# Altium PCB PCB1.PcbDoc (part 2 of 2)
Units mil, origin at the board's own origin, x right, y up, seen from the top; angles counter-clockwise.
Board outline 1968.5 x 1968.5 mil, 2 copper layers (Top Layer, Bottom Layer); 81 components, 57 nets, 327 pads, 270 vias.
Unrouted connection lines stored in the file: 104.
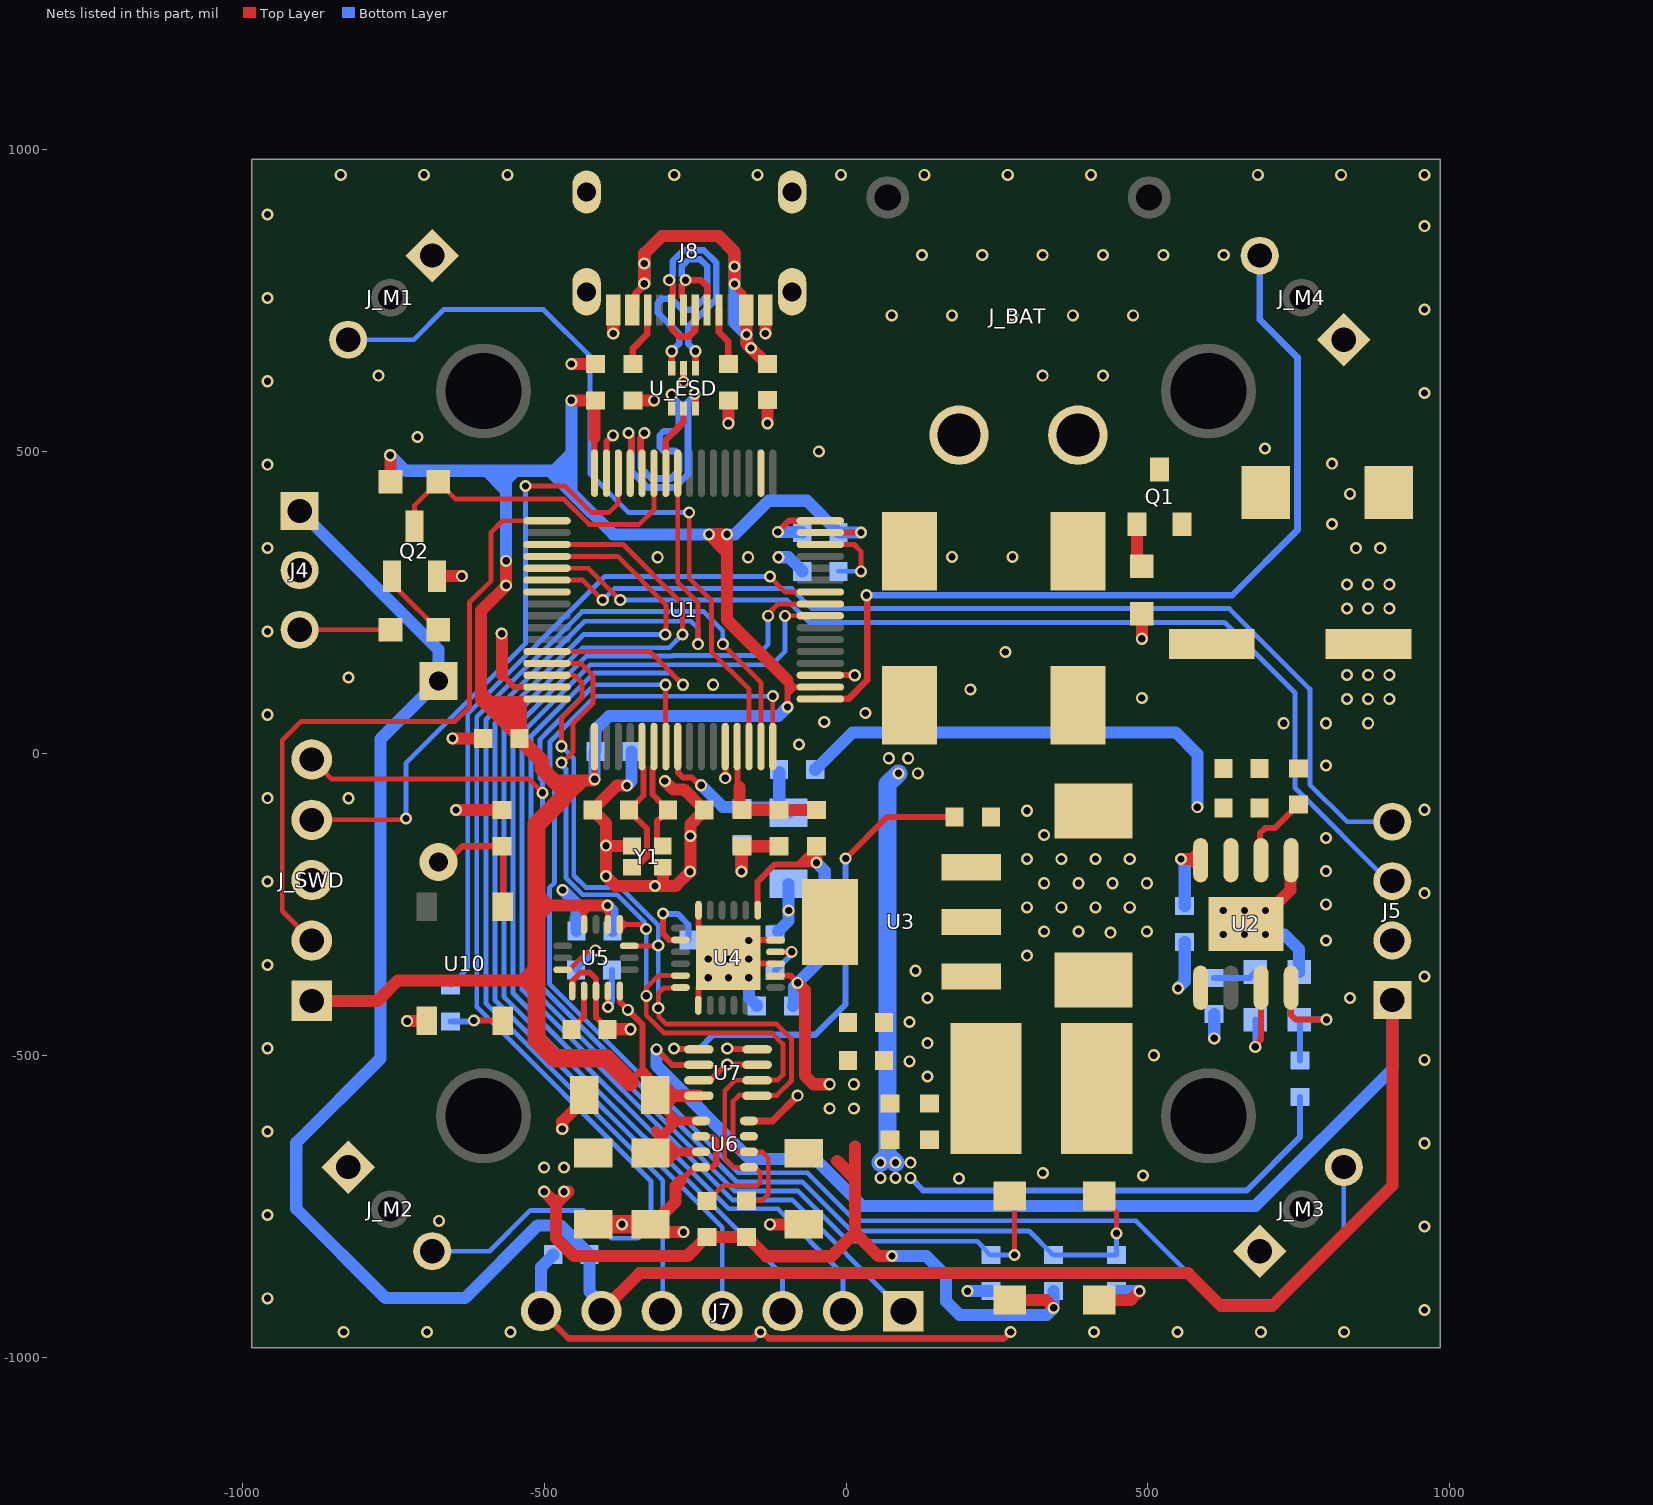
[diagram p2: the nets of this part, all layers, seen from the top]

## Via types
v1: diameter 20, hole 12, Top Layer to Bottom Layer, tented both sides, 270 vias

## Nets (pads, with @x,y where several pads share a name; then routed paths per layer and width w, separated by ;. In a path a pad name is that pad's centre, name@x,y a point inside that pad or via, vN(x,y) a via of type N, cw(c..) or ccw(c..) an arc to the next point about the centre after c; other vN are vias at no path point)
+3.3V: C_BMP1.1 C_BMP2.1 C_BULK.1 C_CS.1 C_INA.1 C_LDO_OUT.1 C_VDD1.1 C_VDD2.1 C_VDD3.1 C_VDD4.1 C_VLOGIC.1 CAP_BYPASS.1 FB2.1 J_SWD.1 R2.1 R4.1 R21.1 R_NRST.1 SW_BOOT.2 U1.1 U1.18 U1.31 U1.48 U1.64 U3.2 U3.4 U4.8 U4.13 U5.2 U5.4 U5.13 U6.2 U6.6 U6.8 U7.4 | length 7789
  Top Layer w10: -604.69,108.07 -586.81,90.19 ; -586.81,71.52 -586.81,90.19 ; -541.08,77.35 U1.64@-528.24,90.19 ; U1.64@-495.27,90.19 U1.64@-528.24,90.19 ; -446.45,-251.97 -434.04,-264.38 ; -432,-251.97 -433.66,-253.63 -433.66,-264 ; -421.63,-251.97 -433.66,-264 ; U1.1@-416.54,11.46 -416.41,11.33 -416.41,-42.64 v1(-416.29,-42.76) ; U1.48@-416.54,464.2 -416.54,523.83 ; -407.41,-251.04 -406.47,-251.97 -395,-263.44 ; v1(-395,-251.97) -394.64,-252.33 -394.64,-283.23 U5.2@-394.45,-283.42 ; U5.13@-374.9,-393.47 U5.13@-374.75,-393.62 U5.13@-374.75,-393.62 -374.71,-411.55 v1(-361.47,-424.79) ; v1@-360.87,-424.79 v1(-361.47,-424.79) ; -349.31,-535 -337,-522.69 ; -337,-533 -337,-522.69 ; -325.69,-534 -337,-522.69 ; U4.13@-146.28,-259.78 -146.28,-212.28 -117.72,-183.72 -79.39,-183.72 ; U4.8@-116.75,-368.05 -116.55,-368.25 -91.75,-368.25 v1(-80,-380) ; v1(-97,77) -97,98.32 ; v1(-49,-181) -51.72,-183.72 -63.16,-183.72 ; -49,-169.56 -59.39,-179.95 ; FB2.1@-49,-158.12 -53.79,-158.12 FB2.1@-59.39,-163.72 ; U1.18@-42.88,110.22 -86.22,110.22 -97,121 -97,98.32 ; U1.18@-42.53,109.88 U1.18@-42.53,109.88 -85.5,109.82 -97,98.32 ; U1.31@-42.53,365.78 v1(24.78,365.78) ; -586.81,90.19 U1.64@-528.24,90.19 ; -434.04,-264.38 -433.66,-264 ; -434.04,-264.38 -434.04,-283.23 U5.4@-433.85,-283.42 -433.66,-283.23 -433.66,-264 ; v1(-361.47,-424.79) -337,-449.26 -337,-522.69 ; -79.39,-183.72 -69.39,-173.72 ; -79.39,-183.72 -63.16,-183.72 ; -69.39,-173.72 FB2.1@-59.39,-163.72 ; -69.39,-173.72 -63.16,-179.95 -63.16,-183.72 ; -63.16,-183.72 -59.39,-179.95 ; -59.39,-179.95 FB2.1@-59.39,-163.72
  Top Layer w15: v1(-416.29,-42.76) -429.26,-42.76 ; C_BMP2.1@-323.69,-661.91 -321.79,-660 -280.89,-660 ; -315.82,-625.07 -305.99,-634.91 ; C_INA.1@-315.82,-566 -315.82,-573.87 -280.89,-608.8 ; C_BMP2.1@-315.31,-644.23 -305.99,-634.91 ; C_BMP2.1@-296.94,-677.06 -280.39,-660.51 ; -291.29,-608.8 -280.89,-608.8 ; -280.39,-609.31 -305.99,-634.91 ; U6.6@-240.27,-660 -280.89,-660 ; U6.8@-240.26,-608.8 -280.89,-608.8 ; -429.26,-42.76 -431.5,-45 -461,-74.5 -469.5,-74.5 -440,-45 -437.76,-42.76 -429.26,-42.76 ; -305.99,-634.91 -280.89,-660
  Top Layer w20: J_SWD.1@-885,-410 -776,-410 -742,-376 -536.25,-376 ; v1(-755,494) -754.37,493.37 R21.1@-754.37,450 ; v1(-563,319) v1(-563,278) -604.69,236.31 -604.69,108.07 -604.69,89.4 -586.81,71.52 C_VDD1.1@-541.08,25.79 ; -513,-396.65 -533.65,-376 -536.25,-376 ; -513,-352.75 -536.25,-376 ; -513,-274 -513,-273.55 -491.42,-251.97 ; -513,-244 -505.03,-251.97 -491.42,-251.97 ; -513,-227 -513,-230.39 -491.42,-251.97 ; v1(-500,-726) -480.31,-745.69 -480.31,-802.98 -450.71,-832.57 -262.44,-832.57 -235.75,-805.88 -234.96,-805.88 R4.1@-230,-800.92 -229.96,-800.88 -165.04,-800.88 R2.1@-165,-800.84 -164.21,-800.84 -132.06,-833 -24,-833 15,-794 ; -482.67,-46.36 -481.31,-45 -440,-45 -431.5,-45 -418.53,-45 v1(-416.29,-42.76) ; -476.68,-742.68 v1@-460,-726 ; -469.5,-74.5 -469.5,-59.53 ; v1(-455,585) C_VDD3.1@-415,585 -416.54,583.46 -416.54,523.83 ; v1(-395,-251.97) -406.47,-251.97 -421.63,-251.97 -432,-251.97 -446.45,-251.97 -491.42,-251.97 ; C_INA.1@-315.82,-566 -314.76,-567.06 -284.28,-567.06 ; C_INA.1@-300.7,-583.48 -284.28,-567.06 ; C_INA.1@-300.7,-550.64 -284.28,-567.06 ; U7.4@-243.76,-567.06 -284.28,-567.06 ; -97,121 -197,221 -197,333 ; v1(-80,-380) -67.86,-392.14 -67.86,-533.84 -53.7,-548 v1(-27,-548) ; v1(-49,-181) -49,-169.56 -49,-158.12 FB2.1@-48.64,-157.76 ; U3.4@-48.64,-257.15 U3.4@-26.57,-279.21 ; -15,-675 15,-705 ; 15,-651 15,-705 ; v1(76,-832.58) 53.58,-832.58 15,-794 ; SW_BOOT.2@271,-905.25 330.85,-905.25 v1(344,-918.4) ; -197,333 v1(-197,363) v1(-227,363) -197,333 ; 15,-794 15,-705
  Top Layer w25: -576,80 -574,78 -570,78 -569.35,77.35 ; -469.5,-59.53 -482.67,-46.36 -503.26,-25.77 -503.26,-13.6 -541.08,24.21 C_VDD1.1@-541.08,25 -541.08,25.79 -541.08,49.08 ; -569.35,77.35 -541.08,49.08 ; -569.35,77.35 -541.08,77.35 -541.08,49.08
  Top Layer w30: -513,-274 -513,-352.75 -513,-396.65 -513,-474.3 -482.29,-505.01 -396.99,-505.01 -358,-544 ; -513,-273.55 -513,-244 -513,-230.39 ; -513,-227 -513,-118 -469.5,-74.5
  Bottom Layer w20: v1(-755,494) -729.22,468.22 -596,468.22 ; v1(-563,278) v1(-563,319) -563,438 ; v1(-455,585) -455,497 ; v1(-416.29,-42.76) C_VDD2.1@-416.29,1.63 ; C_VDD2.1@-414.92,3 -414.92,39.82 -392.9,61.84 -112.16,61.84 v1(-97,77) ; v1(-395,-251.97) -386.61,-260.37 CAP_BYPASS.1@-386.61,-294.38 ; C_VLOGIC.1@-88,-418 -86.43,-416.43 -86.43,-386.43 v1(-80,-380) -35.17,-335.17 -35.17,-194.83 v1(-49,-181) ; v1(24.78,365.78) C_VDD4.1@-12.61,365.78 -12.61,366.56 -64.61,418.56 -128.44,418.56 -184,363 v1(-197,363) v1(-227,363) -385.83,363 -455,432.17 ; v1(76,-832.58) 133.18,-832.58 166,-865.4 166,-908 188,-930 333,-930 v1@344,-919 ; v1(344,-918.4) R_NRST.1@344,-890.84 ; -596,468.22 -565.78,438 -563,438 ; -596,468.22 -564.22,468.22 ; -564.22,468.22 -563,467 -563,452.5 ; -564.22,468.22 -547.28,468.22 ; -563,438 -563,452.5 ; -563,452.5 -547.28,468.22 ; -547.28,468.22 -491.05,468.22 ; -491.05,468.22 -473.03,450.2 ; -491.05,468.22 -483.78,468.22 ; -483.78,468.22 -468.78,468.22 -455,482 ; -483.78,468.22 -455,497 ; -473.03,450.2 -455,468.22 ; -473.03,450.2 -455,432.17 ; -455,432.17 -455,468.22 ; -455,468.22 -455,482 ; -455,482 -455,497
  other v1: -467,-726 -500,-686 -467,-686 -27,-588 13,-588 13,-548
+5V_SYS: C_LORA.1 D5.1 J4.1 J5.1 J7.6 U7.2 | length 5448.2
  Top Layer w10: v1(-313.97,-490.14) -288.24,-515.87 U7.2@-243.76,-515.87
  Top Layer w20: J7.6@-405,-924 -341.92,-860.92 566.92,-860.92 620.96,-914.96 706.04,-914.96 905,-716 J5.1@905,-408.43
  Bottom Layer w20: J4.1@-905,401.85 -675,171.85 D5.1@-675,120 -771,24 -771,-505.27 -910.69,-644.96 -910.69,-754.31 -763,-902 -631,-902 -511,-782 -473.08,-782 -430.83,-824.25 -430.04,-824.25 -425.08,-829.21 -425.08,-891.22 -405,-911.3 J7.6@-405,-924 ; v1(-313.97,-490.14) -313.97,-517.1 -159.19,-671.89 -50.95,-671.89 26.65,-749.49 678.51,-749.49 905,-523 J5.1@905,-408.43
BOOT0: R_BOOT.1 SW_BOOT.1 U1.60 | length 2053.4
  Top Layer w8: U1.60@-495.27,168.93 -325.11,168.93 v1(-270,113.82) ; SW_BOOT.1@271,-733.21 279,-741.21 v1(279,-831)
  Bottom Layer w8: v1(-270,113.82) -289.18,133 -417.54,133 -521.67,28.86 -521.67,-387.98 -184.92,-724.74 -79.77,-724.74 3.73,-808.23 217.23,-808.23 228.25,-819.25 228.25,-820.04 239.21,-831 v1(279,-831)
BST: C_BST.1 U2.8 | length 151
  Top Layer w15: U2.8@582.92,-187.75 570.17,-175 582.92,-162.25 U2.8@582.92,-160.87
  Top Layer w20: v1(555,-175) 570.17,-175 585.34,-175 587.29,-176.95 U2.8@587.56,-176.95
  Bottom Layer w20: v1(555,-175) 561.13,-181.13 C_BST.1@561.13,-252.64
GND: C1.2 C2.2 C3.2 C5.2 C6.2 C7.2 C8.2 C14.2 C22.2 C_BMP1.2 C_BMP2.2 C_BULK.2 C_COMP.2 C_CPOUT.1 C_CS.2 C_INA.2 C_LDO_IN.2 C_LDO_OUT.2 C_LORA.2 C_NRST.2 C_REGOUT.2 C_RES.2 C_VBUS.2 C_VCAP.2 C_VDD1.2 C_VDD2.2 C_VDD3.2 C_VDD4.2 C_VDDA1.2 C_VDDA2.2 C_VLOGIC.2 CAP_BYPASS.2 D1.2 D2.2 J4.2 J5.2 J7.7 J8.1 J8.2 J8.3 J8.4 J8.A1B12 J8.B1A12 J_BAT.2 J_M1.1 J_M2.1 J_M3.1 J_M4.1 J_SWD.3 Q2.2 R1.2 R3.2 R7.2 R_BOOT.2 R_CC1.2 R_CC2.2 R_FREQ.2 SW_RST.2 U1.12 U1.19 U1.32 U1.47 U1.63 U2.5 U2.9 U3.1 U4.1 U4.9 U4.11 U4.18 U4.25 U5.9 U5.11 U6.1 U6.5 U6.7 U7.3 U7.7 U7.8 U10.3 U_ESD.2 Y1.2 Y1.4 | length 5612
  Top Layer w10: -570,129.92 -569.21,129.92 -559.25,119.96 -559.25,119.49 -549.64,109.88 U1.63@-495.27,109.88 ; J7.7@-505,-924 -459.75,-969.25 -155.04,-969.25 -144.24,-958.45 v1(-141.53,-958.45) -138.82,-958.45 -128.02,-969.25 261.94,-969.25 272.75,-958.45 v1(272.8,-958.45) ; U5.9@-453.55,-393.62 -453.36,-393.43 -453.36,-377.21 -439.12,-362.97 -424.59,-362.97 -414.15,-373.41 -414.15,-393.24 U5.11@-413.96,-393.43 ; U5.11@-414.15,-393.62 -414.15,-437.09 C_RES.2@-395.08,-456.16 ; U1.47@-396.85,464.2 -396.85,516.52 -386.37,527 v1(-386,527) ; -273.83,-708.17 -253.4,-687.75 -251.53,-687.75 -249.38,-685.6 U6.5@-240.26,-685.6 -239.44,-684.78 -220.73,-684.78 -214.95,-679 -214.95,-641.08 -220.81,-635.22 -239.44,-635.22 U6.7@-240.27,-634.4 ; v1(-269,615.53) U_ESD.2@-269,638.17 ; U4.1@-244.7,-417.26 -244.5,-417.06 -244.5,-388.02 U4.25@-195,-338.52 ; U4.18@-244.39,-259.78 -244.19,-259.98 -244.19,-289.33 U4.25@-195,-338.52 ; U7.3@-243.76,-541.46 -224.99,-541.46 -198.82,-515.29 v1(-196.77,-515.29) -196.48,-515.58 -147.51,-515.58 U7.7@-147.22,-515.87 ; v1(-200,-41) U1.12@-200,11.46 ; v1@-199,-489 -198.36,-489.64 -147.86,-489.64 U7.8@-147.22,-490.28 ; U4.9@-116.75,-348.36 -185.16,-348.36 U4.25@-195,-338.52 ; U4.11@-116.75,-308.99 -165.47,-308.99 U4.25@-195,-338.52 ; v1(-113,367) -94.53,385.47 U1.32@-42.53,385.47 ; U1.19@-42.53,129.56 v1(14.44,129.56)
  Top Layer w12: U6.1@-160.87,-608.8 -121.8,-608.8 v1(-80,-567)
  Top Layer w20: v1(-726.98,-443.54) -695.51,-443.54 U10.3@-694.57,-442.6 ; Q2.2@-677.6,293.66 v1(-636.34,293.66) ; v1(-652,25) C_VDD1.2@-600.92,25 ; v1(-646,-93.91) C22.2@-570,-93.91 ; v1(-570.44,198.43) -570,198 -570,129.92 ; v1(-470,-622) -470,-609.95 -433.93,-573.87 C_INA.2@-433.93,-566 C_INA.2@-433.93,-558.13 ; v1(-455,645) -454.84,644.84 C_VDD3.2@-415,644.84 ; C8.2@-419.48,-93.13 -379.73,-53.37 v1(-362.68,-53.37) ; C_BMP1.2@-418.69,-780.02 C_BMP1.2@-410.82,-780.02 ; C8.2@-414.52,-99.66 -413.73,-99.66 -397.68,-115.72 v1@-397.68,-158.37 ; -397.68,-180.87 -397.68,-183.53 ; C_RES.2@-395.08,-456.94 v1(-357,-456.94) ; v1(-385.55,695.45) J8.B1A12@-385.55,734.44 ; Y1.4@-354.68,-153.27 -392.58,-153.27 v1@-397.68,-158.37 ; R_CC2.2@-353,585 v1(-317.74,585) ; -303.48,-219.41 Y1.2@-303.48,-188.67 ; v1(-300.18,-45.87) -286.17,-59.88 -268.04,-59.88 -239.76,-88.17 -239.76,-88.95 C7.2@-234.8,-93.91 -239.76,-98.87 -239.76,-99.66 -257.68,-117.58 v1@-257.68,-196.13 ; -273.83,-708.17 -282.2,-716.54 -282.2,-742.68 -302.2,-762.68 -302.2,-766.39 -315.82,-780.02 -319.53,-780.02 C_BMP2.2@-323.69,-780.02 -310.71,-793 v1(-269,-793) ; v1(-258.35,-195.81) -281.95,-219.41 -381.64,-219.41 v1(-397.68,-203.37) -397.68,-183.53 ; v1(-195,547) R_CC1.2@-195,585 ; v1(-172.93,-195.5) -172.64,-195.21 -172.64,-158.72 C_VDDA1.2@-172.64,-157.76 ; C_VDDA1.2@-172.64,-153.76 C_VDDA2.2@-110.64,-153.76 ; v1(-133.59,695.45) J8.A1B12@-133.59,734.44 ; v1(-130,547) C_VBUS.2@-130,585.16 ; v1(-126.06,-780.06) C_CS.2@-70,-780.06 C_CS.2@-56.38,-793.68 ; SW_RST.2@419.68,-905.25 471.75,-905.25 v1(486.16,-890.84) ; v1(490,190) R1.2@490,231.26 ; U2.9@662.56,-282.56 680.08,-282.56 736.64,-226 736.64,-177.87 U2.5@737.56,-176.95 ; -397.68,-183.53 v1@-397.68,-158.37
  Top Layer w30: C_BMP1.2@-418.69,-780.02 C_BMP2.2@-319.53,-780.02
  Bottom Layer w10: J7.7@-505,-924 -459.75,-969.25 -152.39,-969.25 v1(-141.53,-958.45) v1(-141.53,-958.45) -138.82,-958.45 -128.02,-969.25 261.94,-969.25 272.75,-958.45 v1(272.8,-958.45)
  Bottom Layer w20: J7.7@-505,-924 -505,-850.87 -484.92,-830.79 C_LORA.2@-484.92,-830 ; v1(-469.38,-226.25) -446.45,-249.18 CAP_BYPASS.2@-446.45,-294.38 ; v1(-362.68,-53.37) -355.08,-45.77 C_VDD2.2@-355.08,3 ; C_CPOUT.1@-201,-309 -162,-309 v1(-161,-310) ; v1(-172.93,-195.5) -172.64,-195.21 R7.2@-172.64,-149.88 ; v1(-161,-371.42) -161,-404.06 -147.84,-417.21 C_VLOGIC.2@-147.84,-418 ; v1(-113,367) -73.67,367 C_VDD4.2@-72.45,365.78 ; C_REGOUT.2@-112.25,-295.2 -112.25,-294.41 -95,-277.16 v1(-95,-260) C14.2@-95,-216.02 ; v1(-112,325) -94.94,325 -72.45,302.51 C_VCAP.2@-72.45,301.73 ; v1(201.16,-890.84) R_BOOT.2@240,-890.84 ; C_NRST.2@448,-890.84 v1(486.16,-890.84) ; v1(610,-472) C_COMP.2@610,-431.55 ; v1(695,-300) 726.18,-300 750.47,-324.29 750.47,-361.73 R3.2@751,-362.26
  other v1: -832.08,-958.45 -693.97,-958.45 -555.86,-958.45 410.91,-958.45 549.02,-958.45 687.13,-958.45 825.24,-958.45 958.45,-921.97 -958.45,-902.72 958.45,-783.86 -371.19,-780.02 -674.25,-774.25 -958.45,-764.61 187,-704 492,-699 326,-695 958.45,-645.75 -958.45,-626.5 135,-535 105,-510 958.45,-507.64 510,-500 -196.77,-489 -958.45,-488.39 135,-480 105,-445 135,-405 835,-405 -228,-371.42 -194.5,-371.42 958.45,-369.53 115,-360 -958.45,-350.28 -228,-340.71 -194.5,-340.71 -161,-340.71 300,-335 795,-310 625,-300 660,-300 438.33,-296.89 328.33,-295 385,-295 498.33,-295 625,-260 660,-260 695,-260 300,-255 356.67,-255 413.33,-255 470,-255 795,-250 958.45,-231.42 -316.48,-219.41 328.33,-215 385,-215 441.67,-215 498.33,-215 -958.45,-212.17 795,-195 300,-175 356.67,-175 413.33,-175 470,-175 -397.71,-152.78 795,-140 -257.82,-136.68 328.33,-135 300,-95 958.45,-93.31 -958.45,-74.06 -824.25,-74.25 795,-20 -78,15 725,50 795,50 865,50 -36,52 -958.45,64.05 32,67 830,90 865,90 900,90 490,92 206,106 -220,113.82 -824.25,125.75 830,130 865,130 900,130 264,168 -958.45,202.16 830,240 865,240 900,240 830,280 865,280 900,280 -312,325 -162,325 175.75,325.75 275.75,325.75 845,340 885,340 -958.45,340.27 805,380 835,430 -958.45,478.38 805,480 -45,500 694,505 -710,524 958.45,597.24 -958.45,616.49 -774.25,625.75 325.75,625.75 425.75,625.75 75.75,725.75 175.75,725.75 275.75,725.75 375.75,725.75 475.75,725.75 958.45,735.35 -958.45,754.6 125.75,825.75 225.75,825.75 325.75,825.75 425.75,825.75 525.75,825.75 625.75,825.75 958.45,873.46 -958.45,892.71 -836.98,958.45 -698.87,958.45 -560.76,958.45 -284.54,958.45 -146.43,958.45 -8.32,958.45 129.79,958.45 267.9,958.45 406.01,958.45 682.23,958.45 820.34,958.45 958.45,958.45
GPS_RX: J5.4 U1.54 | length 1674.4
  Top Layer w8: U1.54@-495.27,287.04 -436.04,287.04 v1(-403,254)
  Bottom Layer w8: v1(-403,254) -384,273 -89.67,273 -56.7,240.03 635.06,240.03 768.52,106.57 768.52,-51.55 830.12,-113.15 J5.4@905,-113.15
GPS_TX: J5.3 U1.53 | length 1707.2
  Top Layer w8: U1.53@-495.27,306.73 -426.73,306.73 v1(-374,254)
  Bottom Layer w8: v1(-374,254) -97.58,254 -60.7,217.13 626.98,217.13 744,100.1 744,-57.28 898.29,-211.58 J5.3@905,-211.58
I2C1_SCL: R4.2 U1.61 U4.23 U5.1 U6.4 U7.6 | length 1613.2
  Top Layer w8: U1.61@-495.27,149.25 -439.25,149.25 -418.86,128.86 -418.86,82.84 -452,49.7 -452,2.52 -469.84,-15.31 v1@-470.93,-15.31 ; U5.1@-374.75,-283.42 -365.36,-283.42 ; U5.1@-372.99,-291.05 -365.36,-283.42 ; U5.1@-372.99,-275.61 -372.99,-275.79 -365.36,-283.42 ; v1(-331,-291) -333.43,-291 -341.01,-283.42 -365.36,-283.42 ; v1(-330.79,-401.57) -330.12,-400.91 -330.12,-387.12 -311.05,-368.05 U4.23@-274.23,-368.05 ; v1@-330.79,-398.32 -330.79,-433.85 -301.64,-463 -123,-463 -104.45,-481.55 -104.45,-532.45 -112.73,-540.73 U7.6@-145,-540.73 ; R4.2@-230,-741.08 -229.21,-741.08 -204.17,-716.04 -147.86,-716.04 -142,-710.18 -142,-693.61 -147.86,-687.75 -149.6,-687.75 -151.75,-685.6 -185.65,-685.6 -200.95,-670.3 -200.95,-559.12 -183.29,-541.46 -145.46,-541.46 U7.6@-145,-541
  Bottom Layer w8: v1(-471.24,-15.31) -471.24,-18.56 -464,-25.81 -464,-206.17 -436.2,-233.97 -379.17,-233.97 -333.3,-279.84 -333.3,-288.7 v1(-331,-291) ; v1@-330.89,-291.11 -330.89,-401.47 v1(-330.79,-401.57)
I2C1_SDA: R2.2 U1.62 U4.24 U5.16 U6.3 U7.5 | length 1493.5
  Top Layer w8: U1.62@-495.27,129.56 -450.45,129.56 -437.16,116.27 -437.16,92.06 -471.24,57.98 v1(-471.24,11.87) ; U5.16@-359.05,-318.82 -311.82,-318.82 v1(-311,-318) ; U4.24@-274.23,-387.73 -274.81,-388.31 -287.18,-388.31 -287.59,-388.72 -302.17,-388.72 -311,-397.55 v1(-311,-422) -310.07,-422.93 -310.07,-436.18 -297.79,-448.47 -114.53,-448.47 -90.54,-472.46 -90.54,-542.61 -114.5,-566.57 -146.73,-566.57 U7.5@-147.22,-567.06 ; R2.2@-165,-741 -139.45,-741 -128.74,-730.29 -128.74,-670.26 -139,-660 U6.3@-160.86,-660 -161.54,-659.33 -179.22,-659.33 -186.92,-651.63 -186.92,-575.92 -177,-566 -168.7,-566 -168.37,-566.33 -156.33,-566.33 U7.5@-156,-566
  Bottom Layer w8: v1(-471.24,11.87) -451,-8.38 -451,-202.2 -431.23,-221.97 -373.75,-221.97 -311,-284.73 v1(-311,-422)
LORA_AUX: J7.5 U1.41 | length 1844.8
  Top Layer w8: U1.41@-278.74,464.2 -278.74,283.33 -245,249.59 v1(-245,181)
  Bottom Layer w8: J7.5@-305,-920 -303.69,-918.69 -303.69,-707.01 -596.58,-414.12 -596.58,55.35 -566.97,84.97 -447.47,204.47 -432.93,219 -256.83,219 -245,207.17 v1(-245,181)
LORA_M0: J7.1 U1.24 | length 1885
  Top Layer w8: v1(-101,227.94) U1.24@-42.53,227.99
  Bottom Layer w8: v1(-101,227.94) -101,169 -123,147 -423.82,147 -436.22,134.59 -515.91,54.91 -536.65,34.16 -536.65,-391.38 -188.37,-739.66 -89.34,-739.66 91,-920 J7.1@95,-920
LORA_M1: J7.2 U1.25 | length 1857.7
  Top Layer w8: v1@-126,227 -126.7,227.7 -126.7,233.48 -112.52,247.67 U1.25@-43.2,247.67
  Bottom Layer w8: v1(-129,227.94) -129,181 -148,162 -286.91,162 -287.41,161.5 -429.6,161.5 -551.64,39.46 -551.64,-397.07 -194.3,-754.4 -113.33,-754.4 -5,-862.73 J7.2@-5,-920
LORA_RX: J7.4 U1.52 | length 1750
  Top Layer w8: U1.52@-495.27,326.41 -378.41,326.41 -298.44,246.43 v1@-298.44,196.43
  Bottom Layer w8: v1@-298.44,197 v1(-299.44,197) -434.65,197 -581.6,50.06 -581.6,-408.44 -205,-785.04 J7.4@-205,-920
LORA_TX: J7.3 U1.51 | length 1830.5
  Top Layer w8: U1.51@-495.27,346.1 -369.1,346.1 -271,248 v1(-271,197)
  Bottom Layer w8: v1(-271,197) -293,175 -436.37,175 -442.45,168.93 -551.69,59.69 -566.62,44.76 -566.62,-402.75 -105,-864.37 J7.3@-105,-920
NetC1_1: C1.1 C2.1 C3.1 D1.1 Q1.2 R6.1 U2.7 | length 762
  Bottom Layer w20: R6.1@-50.91,-27 -50.91,-26.21 -45.94,-21.25 -45.16,-21.25 11.09,35 546,35 582,-1 v1(582,-89)
NetC5_1: C5.1 C6.1 D3.2 L1.2 R5.1 | length 1431.8
  Bottom Layer w10: v1(107,-703) 128,-724 663.53,-724 752,-635.53 R5.1@752,-568.84
  Bottom Layer w30: v1(57,-678) 69,-666 ; v1(82,-678) 69,-665 69,-51 v1(87,-33)
  other v1: 57,-703 82,-703 107,-678 119,-33 71,-8 103,-8
NetC22_1: C22.1 D5.2 U10.1 | length 216.3
  Top Layer w10: D5.2@-675,-180 -661.73,-180 -635.48,-153.76 C22.1@-570,-153.76 -568.58,-155.17 -568.58,-181.42 U10.1@-568.58,-253.62
NetC_COMP_1: C_COMP.1 R_COMP.2 | length 71.9
  Bottom Layer w10: C_COMP.1@610,-371.71 668.55,-371.71 R_COMP.2@678,-362.26
NetC_CPOUT_2: C_CPOUT.2 U4.20 | length 142.3
  Top Layer w10: v1(-303,-265) -303,-299.05 -293.25,-308.79 -274.43,-308.79 U4.20@-274.23,-308.99
  Bottom Layer w10: v1(-303,-265) -301.68,-266.32 -278,-266.32 -260.84,-283.48 C_CPOUT.2@-260.84,-309
NetC_LDO_IN_1: C_LDO_IN.1 D3.1 D4.1 U3.3 U7.1 | length 805
  Top Layer w10: v1(-285,-489) -284.36,-489.64 -244.4,-489.64 U7.1@-243.76,-490.28 ; v1(-0.58,-174) 68.42,-105 C_LDO_IN.1@180.08,-105
  Bottom Layer w10: v1@-282.31,-489.64 -243.19,-489.64 -219.6,-466.04 -50.95,-466.04 -0.58,-415.67 v1(-0.58,-174)
NetC_REGOUT_1: C_REGOUT.1 U4.10 | length 70.1
  Top Layer w10: U4.10@-116.75,-328.68 v1(-90,-328.68)
  Bottom Layer w10: C_REGOUT.1@-118,-360 -117.21,-360 -91.91,-334.7 -91.91,-330.59 v1(-90,-328.68)
NetC_RES_1: C_RES.1 U5.10 | length 72.1
  Top Layer w10: C_RES.1@-454.92,-456.94 -454.92,-456.16 -433.85,-435.09 U5.10@-433.85,-393.62
NetC_SR_1: C_SR.1 U5.12 | length 94.4
  Top Layer w10: v1@-395.85,-421.79 v1(-394.3,-420.24) -394.45,-420.09 U5.12@-394.45,-393.62 U5.12@-394.6,-393.47
  Bottom Layer w10: v1@-395.08,-421.02 -395.08,-418.31 -387.53,-410.77 C_SR.1@-387.53,-358.84
NetC_SR_2: C_SR.2 U5.8 | length 115.7
  Top Layer w8: U5.8@-469.25,-358.22 -458.22,-358.22 -428.48,-328.48 -417.51,-328.48 v1(-415.21,-326.19)
  Bottom Layer w10: C_SR.2@-447.38,-358.84 -447.38,-358.06 -437.41,-348.1 -436.63,-348.1 -416.93,-328.39 v1@-416.93,-323.57
NetC_VBUS_1: C_VBUS.1 D4.2 J8.A4B9 J8.B4A9 | length 876
  Top Layer w12: J8.B4A9@-354.05,734.44 -348.24,740.25 -348.24,762.03 -334.24,776.03 v1(-334.24,778.2) ; v1(-184.61,777.61) -184.61,775.45 -170.89,761.73 -170.89,740.25 J8.A4B9@-165.08,734.44
  Top Layer w20: v1(-334.24,778.2) v1(-334.24,811.58) -334.24,827.81 -304.64,857.41 -211.34,857.41 -184.61,830.68 v1(-184.61,806.61) v1(-184.61,777.61) ; J8.A4B9@-165.08,734.44 -165,734.36 v1(-165,694) -165,679.21 v1(-157.56,671.77) -135.75,649.96 -134.96,649.96 C_VBUS.1@-130,645
  Bottom Layer w20: v1(-334.24,778.2) v1(-334.24,811.58) -334.24,827.76 -304.6,857.4 -211.28,857.4 -184.61,830.73 v1(-184.61,806.61) v1(-184.61,777.61) -184.61,713.61 v1(-165,694) -165,679.21 v1(-157.56,671.77)
NetC_VDDA1_1: C_VDDA1.1 C_VDDA2.1 FB2.2 U1.13 | length 232.6
  Top Layer w10: U1.13@-180.32,11.46 -180,11.14 -180,-51.71 -176.32,-55.39
  Top Layer w20: -176.32,-55.39 -176.32,-90.23 C_VDDA1.1@-172.64,-93.91 C_VDDA2.1@-110.64,-93.91 FB2.2@-48.64,-93.91
NetJ8_A5: J8.A5 R_CC1.1 | length 96
  Top Layer w10.9: J8.A5@-210.36,734.44 -210.36,697.67 -195,682.31 R_CC1.1@-195,644.84
NetJ8_A6: J8.A6 J8.B6 U_ESD.1 | length 489.3
  Top Layer w10.9: v1(-292.75,784) -292.75,781.54 -286.7,775.49 -286.7,756.52 -289.1,754.13 J8.B6@-289.1,734.44 -288.64,733.99 -288.64,703.19 -276.12,690.67 -259.93,690.67 -250.18,700.42 -250.18,733.99 J8.A6@-249.73,734.44 ; U_ESD.1@-249.32,636.42 U_ESD.1@-249.32,638.17 v1(-249.32,666.27)
  Bottom Layer w10.9: v1(-292.75,784) -292.75,786.46 -287.2,792.01 -287.2,815.35 -268.96,833.59 -235.5,833.59 -215.02,813.12 -215.02,752.69 -261.55,706.17 -261.55,678.5 v1(-249.32,666.27)
NetJ8_A7: J8.A7 J8.B7 U_ESD.3 | length 489.9
  Top Layer w10.9: U_ESD.3@-288.69,636.42 U_ESD.3@-288.69,638.17 v1(-288.69,666.27) ; J8.A7@-269.41,734.44 -269.41,754.13 -271.8,756.52 -271.8,775.49 -265.75,781.54 v1(-265.75,784) -240,784 -230.04,774.04 J8.B7@-230.04,734.44
  Bottom Layer w10.9: v1(-288.69,666.27) -276.45,678.5 -276.45,694.62 -311.73,729.9 -311.73,746.08 -304.79,753.02 -288.61,753.02 -270.28,734.69 -254.09,734.69 -246.2,742.59 -229.92,758.86 -229.92,806.95 -241.67,818.69 -260.37,818.69 -272.3,806.76 -272.3,793.01 -265.75,786.46 v1(-265.75,784)
NetJ8_B5: J8.B5 R_CC2.1 | length 99.8
  Top Layer w10.9: R_CC2.1@-353,644.84 -353,671 -328.92,695.08 -328.92,733.99 J8.B5@-328.47,734.44
NetJ_BAT_1: J_BAT.1 Q1.3
NetJ_SWD_2: J_SWD.2 U1.49 | length 1090.4
  Top Layer w8: J_SWD.2@-885,-310 -934,-261 -934,22 -903.32,52.68 -802.68,52.68 -647.78,52.68 -623.69,76.77 -623.69,250.31 -588,286 -588,366.51 -569.04,385.47 U1.49@-495.27,385.47
NetJ_SWD_4: J_SWD.4 U1.46 | length 1018.2
  Top Layer w8: J_SWD.4@-885,-110 -731,-110 v1(-729,-108) ; v1(-531,443.22) -466.05,443.22 -422.02,399.19 -392.39,399.19 -377.17,414.41 U1.46@-377.17,464.2
  Bottom Layer w8: v1(-729,-108) -729,-16.23 -531,181.77 v1(-531,443.22)
NetQ1_1: Q1.1 R1.1 | length 73.1
  Top Layer w20: Q1.1@482.05,379.76 482.05,317.95 R1.1@490,310
NetQ2_1: Q2.1 R20.1 | length 120.5
  Top Layer w8: Q2.1@-752.4,293.66 -741.4,282.66 -741.4,270.77 R20.1@-675.63,205
NetQ2_3: Q2.3 R21.2 U1.43 | length 547.2
  Top Layer w8: Q2.3@-715,376.34 -715,410.63 R21.2@-675.63,450 -647.37,421.74 -467.94,421.74 -425.64,379.44 -342.44,379.44 -318.11,403.77 U1.43@-318.11,464.2
NetR3_1: R3.1 R5.2 U2.4 | length 220.2
  Top Layer w10: U2.4@737.56,-388.17 737.56,-433.41 745.15,-441 v1(796,-441)
  Bottom Layer w10: R5.2@752,-509 752,-442 R3.1@751,-441 v1(796,-441)
NetR25_1: R25.1 U10.4 | length 83
  Top Layer w10: v1@-612.6,-442.6 U10.4@-568.58,-442.6
  Bottom Layer w10: R25.1@-655,-444 -618,-444 v1(-616.6,-442.6)
NetR_COMP_1: R_COMP.1 U2.3 | length 146.8
  Top Layer w10: v1(678,-486) 678,-483.29 687.56,-473.74 U2.3@687.56,-388.17
  Bottom Layer w10: v1(678,-486) R_COMP.1@678,-441
NetR_FREQ_1: R_FREQ.1 U2.6 | length 129.2
  Top Layer w10: U2.6@687.56,-176.95 685.84,-175.23 685.84,-132.16 694.18,-123.82 710.31,-123.82 739.25,-94.88 749.21,-84.92 R_FREQ.1@750,-84.92
NetU1_45: U1.45 U_ESD.6 | length 404.6
  Top Layer w10.9: U1.45@-357.48,464.2 -357.48,497.91 -355.09,500.3 v1@-355.09,523.49 ; v1(-250.84,595.87) -249.32,594.35 U_ESD.6@-249.32,569.49
  Bottom Layer w10.9: v1(-360.14,531) -360.14,528.54 -354.59,522.99 -354.59,466.51 -328.63,440.55 -283.73,440.55 -261.79,462.49 -261.79,582.46 -250.84,593.41 v1(-250.84,595.87)
NetU1_55: U1.55
NRST: C_NRST.1 J_SWD.5 R_NRST.2 SW_RST.1 U1.7 | length 2414.5
  Top Layer w8: J_SWD.5@-885,-10 -884.89,-10 -852.77,-42.12 -525.8,-42.12 v1(-502.67,-65.25) ; v1(-299,113.82) -299,12.03 U1.7@-298.43,11.46 ; SW_RST.1@419.68,-733.21 422.24,-733.21 442.45,-753.43 448,-758.98 v1(448,-795)
  Bottom Layer w8: v1(-299,113.82) -416.44,113.82 -427.63,102.63 -490.63,39.63 -506.69,23.57 -506.69,-41.98 -502.67,-46 -502.67,-207.33 -506.05,-210.7 -506.05,-385.21 -181.39,-709.88 -72.69,-709.88 8.34,-790.91 303.12,-790.91 343.21,-831 R_NRST.2@344,-831 C_NRST.1@448,-831 v1(448,-795)
OSC_IN: C8.1 U1.5 Y1.1 | length 237.9
  Top Layer w10: Y1.1@-354.68,-188.67 -345.88,-179.87 -338.59,-179.87 -329.93,-171.21 -329.93,-124.41 -359.64,-94.7 C8.1@-359.64,-93.91 -335.45,-69.73 -335.45,-24.84 -337.8,-22.5 U1.5@-337.8,11.46
OSC_OUT: C7.1 U1.6 Y1.3 | length 189.6
  Top Layer w10: U1.6@-318.11,11.46 -318.11,-22.5 -320.45,-24.84 -320.45,-68.1 -305.39,-83.17 -304.6,-83.17 -294.64,-93.13 -294.64,-94.7 -304.6,-104.66 -305.39,-104.66 -313.23,-112.5 -313.23,-144.47 -304.43,-153.27 Y1.3@-303.48,-153.27
SBUS_IN: J4.3 R20.2 | length 150.6
  Top Layer w8: J4.3@-905,205 R20.2@-754.37,205
STATUS_LED: U1.34
SW: C_BST.2 D2.1 L1.1 U2.1 | length 81.1
  Bottom Layer w20: v1(550,-389) 561.13,-377.87 C_BST.2@561.13,-312.48
TIM2_CH1: J_M1.3 U1.14 | length 1267.9
  Top Layer w8: v1(-259.74,399) -259.74,290.22 -223.08,253.56 -223.08,168.58 -160.63,106.13 U1.14@-160.63,11.46
  Bottom Layer w8: J_M1.3@-824.6,685.4 -716.28,685.4 -666.26,735.42 -501.21,735.42 -423.99,658.21 -423.99,462.88 -360.11,399 v1(-259.74,399)
TIM2_CH2: J_M2.3 U1.15 | length 2090.8
  Top Layer w8: v1(-204.08,181) -140.95,117.87 U1.15@-140.95,11.46
  Bottom Layer w8: J_M2.3@-685.4,-824.6 -590.6,-824.6 -523,-757 -435,-757 -389,-803 -344.6,-803 -323,-781.4 -323,-708.37 -611.56,-419.81 -611.56,60.65 -437.21,235 -235.83,235 -204.08,203.25 v1(-204.08,181)
TIM2_CH3: J_M3.3 U1.16 | length 2581.1
  Top Layer w8: U1.16@-121.26,11.46 v1@-121.24,94.8
  Bottom Layer w8: v1(-121.22,94.82) -415.16,94.82 -490.24,19.74 -490.24,-33.47 -482.67,-41.05 -482.67,-214.12 -491.42,-222.87 -491.42,-381.46 -178.13,-694.75 -63.88,-694.75 15.65,-774.27 480.35,-774.27 614.08,-908 710,-908 824.6,-793.4 J_M3.3@824.6,-685.4
TIM2_CH4: J_M4.3 U1.17 | length 1470.8
  Top Layer w10.9: U1.17@-42.53,90.19 -42.36,90.36 4.17,90.36 34.89,121.09 34.89,261.11 v1(34,262)
  Bottom Layer w10.9: v1(34,262) 640,262 748,370 748,656 685.4,718.6 J_M4.3@685.4,824.6
USB_DM: U1.44 U_ESD.4 | length 408.3
  Top Layer w10.9: U1.44@-337.8,464.2 -337.8,497.91 -340.19,500.3 -340.19,522.49 -334.14,528.54 v1(-334.14,531) ; U_ESD.4@-288.69,569.49 v1(-288.65,594.36) v1(-288.65,594.36)
  Bottom Layer w10.9: v1(-334.14,531) -334.14,528.54 -339.69,522.99 -339.69,472.69 -322.46,455.45 -289.9,455.45 -284.89,460.46 -276.69,468.66 -276.69,494.44 -283.23,500.98 -302.15,500.98 -308.69,507.52 -308.69,527.14 -302.15,533.68 -283.23,533.68 -276.69,540.22 -276.69,578.37 -276.69,579.94 v1@-288.65,591.9
VBAT_SENSE: C14.1 R6.2 R7.1 U1.8 | length 323.4
  Top Layer w10: U1.8@-278.74,11.46 -278.59,11.3 -278.59,-31.42 -270.2,-39.8 -255.47,-39.8 -242.58,-52.7 v1(-239.87,-52.7)
  Bottom Layer w20: v1(-239.87,-52.7) -204.15,-88.42 -174.26,-88.42 R7.1@-172.64,-90.04 -102.87,-90.04 C14.1@-95,-97.91 ; R6.2@-110.56,-30.62 -110.56,-84.29 -100.87,-93.98 C14.1@-98.94,-93.98
VBUS: U1.42 U_ESD.5 | length 119.2
  Top Layer w10: -269,549 U_ESD.5@-269,571.24
  Top Layer w10.9: U1.42@-298.43,464.2 -298.43,519.57 -269,549
VCAP: C_VCAP.1 U1.30 | length 142.2
  Top Layer w8: U1.30@-42.53,346.1 13.22,346.1 24.73,334.59 v1(24.73,301.73)
  Bottom Layer w8: C_VCAP.1@-12.61,301.73 v1(24.73,301.73)
WS2812: R25.2 U1.26 | length 1151.3
  Top Layer w8: v1(-126,293.06) -126,292.75 -100.6,267.36 U1.26@-42.53,267.36
  Bottom Layer w8: R25.2@-655,-384.16 -654.21,-384.16 -643.25,-373.2 -643.25,-372.41 -626.54,-355.7 -626.54,65.95 -399.43,293.06 v1(-126,293.06)
pads on no net: J8.A8 J8.B8 J_BAT.3 J_BAT.4 J_M1.2 J_M2.2 J_M3.2 J_M4.2 U1.2 U1.3 U1.4 U1.9 U1.10 U1.11 U1.20 U1.21 U1.22 U1.23 U1.27 U1.28 U1.29 U1.33 U1.35 U1.36 U1.37 U1.38 U1.39 U1.40 U1.50 U1.56 U1.57 U1.58 U1.59 U2.2 U4.2 U4.3 U4.4 U4.5 U4.6 U4.7 U4.12 U4.14 U4.15 U4.16 U4.17 U4.19 U4.21 U4.22 U5.3 U5.5 U5.6 U5.7 U5.14 U5.15 U10.2

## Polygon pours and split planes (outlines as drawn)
GND on Top Layer "GND_L01_P000" (solid, remove dead copper, pour order 0): -984.25,-984.25 -984.25,984.25 984.25,984.25 984.25,-984.25
GND on Bottom Layer "GND_L02_P001" (solid, remove dead copper, pour order 1): -984.25,-984.25 -984.25,984.25 984.25,984.25 984.25,-984.25

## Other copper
Top Layer:
  region net NetC1_1: 650,-215 660,-205 660,-120.69 655,-115.69 655,35 745,125 745,470 735,480 588.9,480 530,421.1 530,-55 615,-140 615,-205 625,-215
  region net +3.3V: 25,-673 5,-693 -106,-693 -112,-687 -112,-653 -125,-640 -168,-640 -170,-638 -170,-632 -167,-629 -79,-629 -44,-594 -44,-382 -71,-355 -71,-217 -63,-209 54,-209 100,-255 255,-255 260,-260 260,-320 255,-325 80,-325 25,-380
  pour cut-out: -405,-924 -405,-848 -389,-832
  pour cut-out: -509,-52 -509,-85.8 -492.1,-102.7
  pour cut-out: 450,590.2 476.2,590.2 497,611 497,573 503,567
  pour cut-out: -726.68,177.31 -683.69,177.31 -673,188
  pour cut-out: -782.05,232.68 -782.05,251.95 -761,273
  pour cut-out: -588,223 -512,223 -503,232
  pour cut-out: -275,132 -185.08,132 -170.08,147
  pour cut-out: 482.28,-600.39 ccw(c600.39,-600.39) 600.39,-718.5 ccw(c600.39,-600.39) 718.5,-600.39 ccw(c600.39,-600.39) 600.39,-482.28 ccw(c600.39,-600.39)
  pour cut-out: -718.5,600.39 ccw(c-600.39,600.39) -600.39,482.28 ccw(c-600.39,600.39) -482.28,600.39 ccw(c-600.39,600.39) -600.39,718.5 ccw(c-600.39,600.39)
  pour cut-out: 482.28,600.39 ccw(c600.39,600.39) 600.39,482.28 ccw(c600.39,600.39) 718.5,600.39 ccw(c600.39,600.39) 600.39,718.5 ccw(c600.39,600.39)
  pour cut-out: -718.5,-600.39 ccw(c-600.39,-600.39) -600.39,-718.5 ccw(c-600.39,-600.39) -482.28,-600.39 ccw(c-600.39,-600.39) -600.39,-482.28 ccw(c-600.39,-600.39)
  pour cut-out: 166,37 207,37 218,26
  pour cut-out: 20,95 62,95 74,107
  pour cut-out: -14,147 29,147 35,153
  pour cut-out: 18.68,359.28 49.17,359.28 70.32,338.13
  pour cut-out: -353.09,-294.31 -332.37,-276.58 -289.74,-276.58
  pour cut-out: 468.5,-433.5 186.5,-433.5 170,-450 170,-662 182,-674 471,-674 485,-660 485,-450
  region net +3.3V: -474,-668 -499.17,-668 -512,-680.83 -512,-735 -505,-742 -452,-742 -443,-733 -443,-697 -433,-687 -290,-687 -284.5,-681.5 -284.5,-552.5 -311,-526 -362,-526 -378,-542 -378,-596 -411,-629 -435,-629
  region net NetC5_1: 157,13 133,-11 133,-41 126,-48 69,-48 58,-37 58,146 62,150 153,150 157,146
  region net NetC_VBUS_1: -137,665 -147,655 -147,627 -139,619 -126,619 -44,619 9,566 9,451 58,402 58,270 65,263 146,263 152,269 152,423 110,465 110,604 49,665
  pour cut-out: -257.68,-203.37 -257.68,-70.24 -274.55,-53.37 -292.68,-53.37 -307.68,-38.37 -307.68,51.63 -317.68,61.63 -337.68,61.63 -347.68,51.63 -347.68,-38.37 -362.68,-53.37 -379.73,-53.37 -397.68,-71.32 -397.68,-203.37 -380.05,-221 -275.31,-221
  region net NetJ_BAT_1: 450,580 540,490 540,455 530,445 330,445 315,460 315,565 330,580
  region net NetC5_1: 138,-665 122,-681 122,-722 116,-728 53,-728 45,-720 45,-625 55,-615 155,-615 172,-598 172,-448 180,-440 290,-440 300,-450 300,-660 295,-665
  region net GND: 45,-385 90,-340 260,-340 278,-322 278,-158 265,-145 230,-145 220,-135 220,-85 270,-35 475,-35 495,-55 495,-170 555,-230 700,-230 720,-210 720,-140 730,-130 761.13,-130 778.98,-112.14 778.98,-58.98 765,-45 715,-45 705,-55 705,-100 700,-105 675,-105 670,-100 670,30 760,120 760,482 778,500 937,500 950,487 950,25 840,-85 840,-305 810,-335 525,-335 495,-305 345,-305 330,-320 330,-375 295,-410 185,-410 157,-438 157,-593 150,-600 50,-600 45,-595
  region net SW: 345,-330 355,-320 465,-320 495,-350 595,-350 600,-355 600,-425 595,-430 500,-430 485,-445 485,-660 475,-670 355,-670 345,-660
  region net NetC_LDO_IN_1: 255,-215 265,-205 265,-165 257,-157 222,-157 208,-143 208,-73.1 281.1,0 425,0 440,15 440,400 425,415 335,415 305,385 305,135 190,20 145,-25 145,-195 165,-215
Bottom Layer:
  pour cut-out: -205,-924 -105,-924 -105,-892.18
  pour cut-out: 466.84,-804.04 487.05,-804.04 502.09,-789
  pour cut-out: 769.33,-595.8 814.62,-595.8 823.41,-604.59
  pour cut-out: 905,-113.15 905,-211.58 858,-164.58 858,-163
  region net +3.3V: -514.81,-679.6 -506.21,-671 -464,-671 -456,-679 -456,-732 -462.04,-738.04 -506.96,-738.04 -514.81,-730.19
  pour cut-out: -158.98,-745.79 -158.98,-797.16 -158.46,-797.67
  pour cut-out: -300,-743 -268.08,-743 -257.56,-732.48
  pour cut-out: -439.83,-626.47 -395.47,-626.47 -380,-611
  pour cut-out: -227,725 -189,725 -180,734
  pour cut-out: -531.63,218.28 -484.63,218.28 -476.63,210.28
  pour cut-out: 37,-681.06 -6.06,-681.06 -15,-690
  pour cut-out: 755,-755 810,-810 820,-810
  pour cut-out: 511,-803 511,-775 538,-748
  pour cut-out: 166,-814 166,-856.44 161.52,-860.92
  pour cut-out: 165,-921 115,-921 108,-914
  pour cut-out: -459.96,-855.75 -448.25,-855.75 -425.08,-832.57
  pour cut-out: -685.4,-824.6 -685.4,-894.6 -673,-907
  region net +3.3V: -40.32,-531.59 -45.79,-537.05 -45.79,-597.58 -38.3,-605.07 24.25,-605.07 30.12,-599.2 30.12,-540.09 21.62,-531.59
  pour cut-out: -716.5,161.5 -716.5,187.5 -703,201
  pour cut-out: 18.09,-522.8 34.89,-506 46,-506
  pour cut-out: -678.75,-407.12 -678.75,-421.04 -661.96,-421.04 -651,-432
  pour cut-out: -668.68,115.63 -612.19,115.63 -589.08,92.52
  pour cut-out: -54,281 15,281 34,262
  pour cut-out: 665,285 665,218 659,212
  pour cut-out: -5,-924 95,-924 96,-923 96,-910
  region net NetC5_1: 118,10 137,-9 137,-48 126,-59 45,-59 35,-49 35,-5 50,10
  region net NetC5_1: 68,-650 83,-665 111,-665 120,-674 120,-711 116,-715 49,-715 37,-703 37,-659.12 45.44,-650.68

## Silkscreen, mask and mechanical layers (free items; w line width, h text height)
Top Overlay:
  lines w6: -112,-56 -91,-35 -34,-35 ; 32,15 32,-8 108,-84 144,-84
Bottom Overlay:
  text "GND" at -748,878.07 h30 r315
  text "CH4" at 729.07,875 h30 r225
  text "GND" at 873.07,741 h30 r225
  text "CH1" at -887,725.07 h30 r315
  text "+5V_SYS" at -643.04,396 h30
  text "GND" at -763,291 h30
  text "SBUS_IN" at -648.04,187 h30
  text "NRST" at -716.99,-31 h30
  text "SWD_4" at -687,-115.67 h30
  text "RX" at 810,-121 h30 r270
  text "GND" at -746.98,-214 h30
  text "TX" at 810,-227 h30 r270
  text "SWD_2" at -687,-324 h30
  text "GND" at 810,-346 h30 r270
  text "+3.3V" at -692,-422 h30
  text "+5V_SYS" at 815,-573 h30 r270
  text "GND" at -865.07,-745 h30 r45
  text "CH3" at 908,-802.93 h30 r315
  text "AUX" at -306.1,-840 h30 r270
  text "RX" at -213,-840 h30 r270
  text "TX" at -108,-840 h30 r270
  text "M1" at -13,-840 h30 r270
  text "M0" at 88,-840 h30 r270
  text "+5V_SYS" at -357,-843 h30 r270
  text "GND" at -560,-858 h30 r270
  text "CH2" at -735.07,-879 h30 r45
  text "GND" at 772,-937.93 h30 r315
Mechanical 1:
  the board outline again, w10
